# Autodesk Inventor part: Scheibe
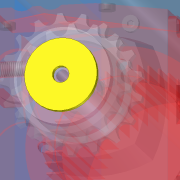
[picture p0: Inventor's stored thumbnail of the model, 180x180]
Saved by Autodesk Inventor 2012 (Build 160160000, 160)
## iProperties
Company: CAD-Verlag
Shininess: 64.0
Length Units: 11269
Angle Units: 11279
Time Units: 11290
Mass Units: 11283
Length Display Precision: 3
Angle Display Precision: 2
Compacted: True
Part Number: Scheibe
Document SubType Name: Modeling
Created: 2004-09
Material: Standard
Designer: Greiling
Manufacturer: Standard
Standards Organization: Custom
Density: 1 g/cm^3
Density: 0.0
Volumn: 0.0
Area: 0.0
PropertySet Name: Model Information
Control State: 0
Master: False
Checked Out: False
Author: Jürgen Kronas
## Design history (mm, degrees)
sketch "Skizze1"
  geometry: C1 r 5.053 at (-29.75, 0) reference; C2 r 7 at (-29.75, 0); C3 r 30 at (-29.75, 0)
  constraints: 2 centre point, 2 coincident
  dimensions: "d0" = 60 diameter of C3; "d1" = 14 diameter of C2
extrude "Extrusion1" new body sketch "Skizze1" distance "d2" = 5; taper "d3" = 0 deg
node "Volumenkörper1"
node "Volumenkörpern"
node "Oberflächenkörpern"
node "Referenz1"
